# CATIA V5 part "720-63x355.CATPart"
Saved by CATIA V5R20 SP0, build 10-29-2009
Part number: 720-63x355
Definition: NONE
Nomenclature: 720-63x355
Source: Unknown
Description: 720-63x355
Bounding box of the stored display mesh (mm): x 0 to 355, y -31.5 to 31.5, z -31.5 to 31.5
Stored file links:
  C:\Users\Utente\Desktop\IO LAVORO\3D X SITO CF\X SITO\720\720-63x355.CATPart

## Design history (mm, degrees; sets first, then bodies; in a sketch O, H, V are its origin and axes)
Body1 "720-63x355" (main body)
  Solid1: solid without history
